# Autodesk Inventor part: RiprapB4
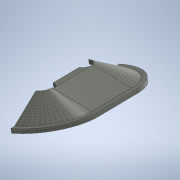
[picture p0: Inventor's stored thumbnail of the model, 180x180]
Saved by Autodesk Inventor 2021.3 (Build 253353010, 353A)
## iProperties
Created: 2021-11
Part Number: RiprapB4
Material: Generic
Document SubType Name: Modeling
Designer: u1426
Density: 1 g/cm^3
Appearance: Rubble - River Rock
Author: u1426
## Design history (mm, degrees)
sketch "Sketch1"
  geometry: L1 (1207.008, -914.4)-(1394.474, -2788.948); L2 (1394.474, -2788.948)-(5858.256, -11716.512); L3 (5858.256, -13024.651)-(6925.056, -13024.651); L4 (6925.056, -13024.651)-(6925.056, -11805.451); L5 (6925.056, -11805.451)-(2287.591, -2530.521); L6 (2287.591, -2530.521)-(2125.969, -914.4); L7 (2125.969, -914.4)-(1207.008, -914.4); L8 (1394.474, -2788.948)-(0, 0); L9 (1207.008, 0)-(0, 0); L10 (5858.256, -13024.651)-(5858.256, -11716.512); L11 (1207.008, 0)-(1207.008, -914.4)
  constraints: 22 end point, 2 horizontal, 2 parallel, 2 perpendicular, 2 vertical, 1 collinear, 1 other
  dimensions: "d0" = 1066.8 distance of L3.start L3.end; "d1" = 1219.2 distance of L3.end L4.end; "d2" = 914.4 distance between parallel lines of L5 L2; "d3" = 914.4 distance between parallel lines of L6 L1; "d20" = 84.2891 deg angle of L1 L7; "d23" = 1207.008 distance of L9.start L8.end; "d24" = 63.4349 deg angle of L8 L9; "d25" = 5858.256 distance from line of L8.end L10 (= SpillPtElev - ToeElev); "d26" = 1874.54794 vertical distance of L1.start L1.end (derived); "d27" = 11716.512 distance from line of L9 L2.end (derived); "d28" = 914.4 distance between parallel lines of L9 L7
extrude "Extrusion1" new body sketch "Sketch1" stored distance "d8" = 14935.2; taper "d9" = 0 deg
sketch "Sketch2"
  geometry: L1 (0, 0)-(-4569.376, 0); L2 (-5858.256, -11716.512)-(-1394.474, -2788.948) reference; L3 (-2287.591, -2530.521)-(-6925.056, -11805.451) reference; L4 (-6925.056, -11805.451)-(-6925.056, -13024.651) reference; L5 (-6925.056, -13024.651)-(-5858.256, -13024.651) reference; L6 (-5858.256, -13024.651)-(-5858.256, -11716.512) reference; L7 (-1394.474, -2788.948)-(-5858.256, -11716.512) reference; L8 (-1394.474, -2788.948)-(-1252.728, -2505.456); L9 (-1252.728, -2505.456)-(-2275.058, -2505.456); L10 (-2287.591, -2530.521)-(-2125.969, -914.4) reference; L11 (-2275.058, -2505.456)-(-2287.591, -2530.521)
  constraints: 8 end point, 2 collinear, 2 horizontal
  dimensions: "d29" = 4605.528 distance from line of L8.end L6 (= TopRRElev - ToeElev)
revolve "Revolution1" sketch "Sketch2" stored, may be unused: angle "d30" = 90 deg
sketch "Sketch3"
  geometry: L1 (-1394.474, 2788.948)-(-5858.256, 11716.512) reference; L2 (-6925.056, 11805.451)-(-2287.591, 2530.521) reference; L3 (-6925.056, 13024.651)-(-6925.056, 11805.451) reference; L4 (-5858.256, 13024.651)-(-6925.056, 13024.651) reference; L5 (-5858.256, 11716.512)-(-5858.256, 13024.651) reference; L6 (-1394.474, 2788.948)-(-1252.728, 2505.456) reference; L7 (-1252.728, 2505.456)-(-1366.123, 2505.456) reference; L8 (-2287.591, 2530.521)-(-2275.058, 2505.456) reference; L9 (0, 0)-(-4606.323, 0); L10 (-5858.256, 0)-(-1252.728, 0) reference; L11 (-2275.058, 2505.456)-(-1366.123, 2505.456) reference
  constraints: 2 end point, 1 point on line
revolve "Revolution2" sketch "Sketch3" stored, may be unused: angle "d31" = 90 deg
sketch "Sketch4"
  geometry: L1 (-7467.6, -2788.948)-(7467.6, -2788.948) reference; L2 (-7467.6, -11716.512)-(-7467.6, -2788.948) reference; L3 (0, 0)-(0, 4154.64); L4 (-7467.6, -2788.948)-(-7467.6, 0); L5 (-7467.6, 0)-(-4678.652, 0); L6 (7467.6, -2505.456)-(7467.6, -2788.948) reference; L7 (7467.6, -2788.948)-(7467.6, 0); L8 (7467.6, 0)-(4678.652, 0); A1 r 2788.948 centre (-7467.6, 0) between (-7467.6, -2788.948) and (-4678.652, 0); A2 r 2788.948 centre (7467.6, 0) between (4678.652, 0) and (7467.6, -2788.948); 1 further point
  constraints: 10 end point, 4 point on circle, 2 centre point, 2 perpendicular, 2 symmetric about line, 1 vertical, 1 other
  dimensions: "d33" = 2788.94794 radius of A1; "d34" = 7467.6 distance from line of L4.end L3
extrude "Extrusion2" cut sketch "Sketch4" extent not by distance; stored distance "d35" = 0; taper "d36" = 0 deg
body "Solid1"
other parameters: "TopRRCapElev" = 865464.36 [user parameter], "ToeElev" = 860813.112 [user parameter; used in 2 equation terms], "TopRRElev" = 865418.64 [user parameter; used in 1 equation term], "SpillPtElev" = 866671.368 [user parameter; used in 1 equation term]
